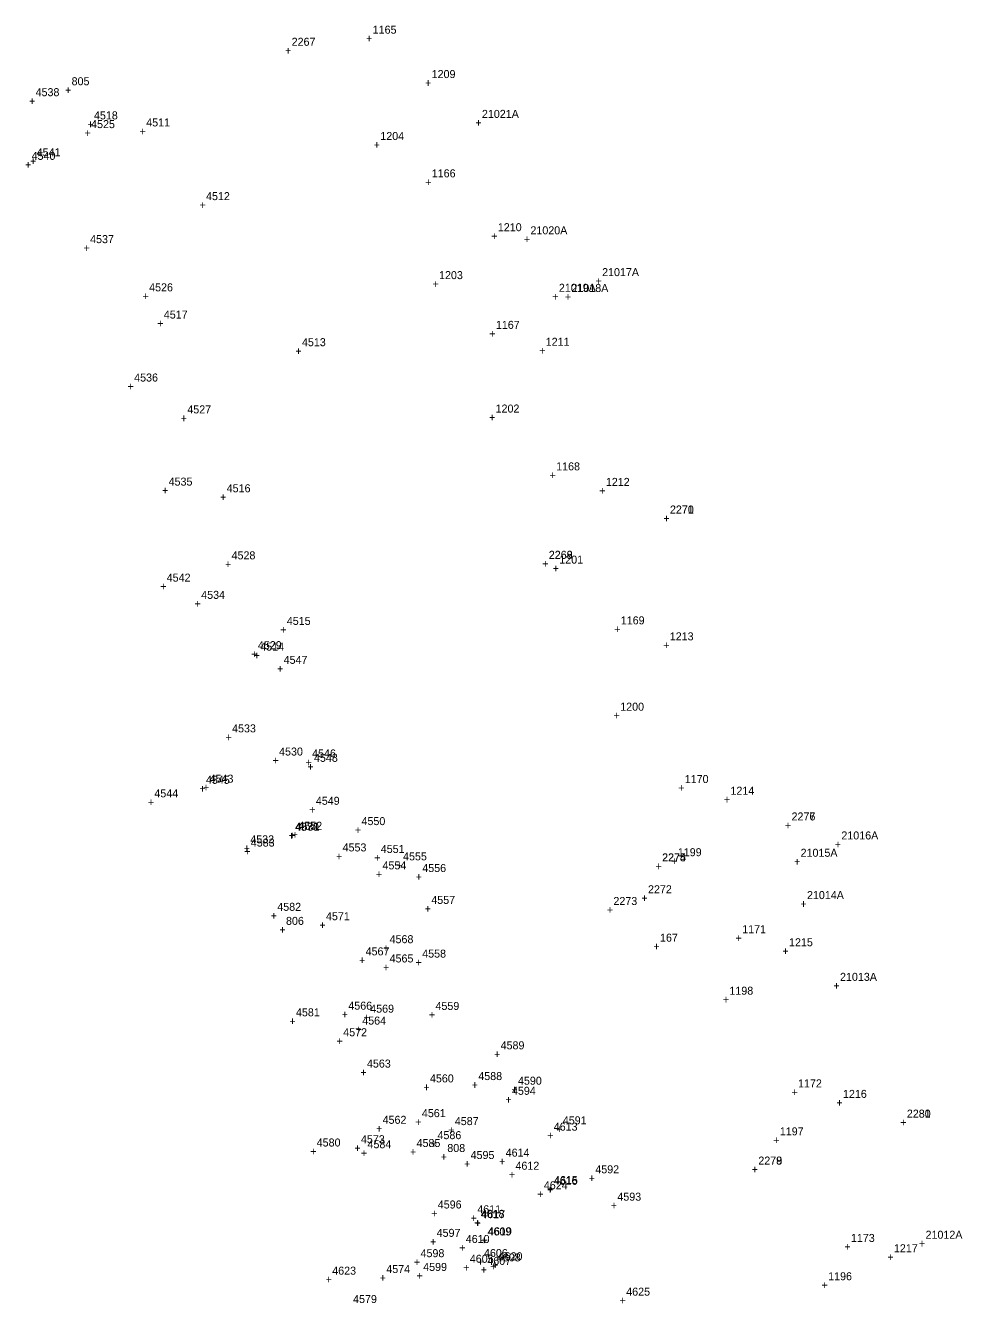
# Model space of a CAD drawing. Extents: x 1036751 to 1042192, y 772604 to 785439.
# Drawn here: x 1037171.7 to 1037464.4, y 782217.4 to 782616.6 of the extents above; entities that cross this region are included whole.
import ezdxf

# ---------------------------------------------------------------- set-up
doc = ezdxf.new("R2010")
doc.units = 0
for name, color, linetype in [('S_Buildings', 7, 'Continuous'), ('S_Buildings_SillElevation', 7, 'Continuous'), ('S_Control_Temp_Traverse', 7, 'Continuous'), ('S_Drainage_Culvert_Top', 7, 'Continuous'), ('S_Drainage_Invert', 7, 'Continuous'), ('S_Drainage_RipRap', 7, 'Continuous'), ('S_Ground_Elevation', 7, 'Continuous'), ('S_Property_BlazedLine', 7, 'Continuous'), ('S_Property_IronPipeFound', 7, 'Continuous'), ('S_Property_Well_Top', 7, 'Continuous'), ('S_Roadway_Centerline', 7, 'Continuous'), ('S_Roadway_Edge_Pavement', 7, 'Continuous'), ('S_Roadway_Edge_TW', 7, 'Continuous'), ('S_Utilities_Pole_Brace3', 7, 'Continuous'), ('S_Utilities_Pole_Power', 7, 'Continuous')]:
    doc.layers.add(name, color=color, linetype=linetype)

msp = doc.modelspace()

# ---------------------------------------------------------------- texts
at = {"layer": 'S_Buildings'}
for s, p in [('4616', (1037336.69, 782254.49)), ('+', (1037334.63, 782251.74)), ('4617', (1037314.1, 782244.07)), ('+', (1037312.04, 782241.32))]:
    msp.add_text(s, height=2.5, dxfattribs=at).set_placement(p)
at = {"layer": 'S_Buildings_SillElevation'}
for s, p in [('4624', (1037333.61, 782253.09)), ('+', (1037331.55, 782250.34))]:
    msp.add_text(s, height=2.5, dxfattribs=at).set_placement(p)
at = {"layer": 'S_Control_Temp_Traverse'}
for s, p in [('805', (1037186.13, 782597.95)), ('805', (1037186.13, 782597.95)), ('805', (1037186.13, 782597.95)), ('805', (1037186.13, 782597.95)), ('+', (1037184.07, 782595.2)), ('+', (1037184.07, 782595.2)), ('+', (1037184.07, 782595.2)), ('+', (1037184.07, 782595.2)), ('806', (1037253.09, 782335.68)), ('806', (1037253.09, 782335.68)), ('806', (1037253.09, 782335.68)), ('806', (1037253.09, 782335.68)), ('806', (1037253.09, 782335.68)), ('+', (1037251.03, 782332.93)), ('+', (1037251.03, 782332.93)), ('+', (1037251.03, 782332.93)), ('+', (1037251.03, 782332.93)), ('+', (1037251.03, 782332.93)), ('167', (1037369.9, 782330.44)), ('167', (1037369.9, 782330.44)), ('+', (1037367.83, 782327.69)), ('+', (1037367.83, 782327.69)), ('+', (1037301.41, 782261.99)), ('+', (1037301.41, 782261.99)), ('808', (1037303.47, 782264.74)), ('808', (1037303.47, 782264.74))]:
    msp.add_text(s, height=2.5, dxfattribs=at).set_placement(p)
at = {"layer": 'S_Drainage_Culvert_Top'}
for s, p in [('+', (1037370.96, 782461.43)), ('2270', (1037373.02, 782464.18)), ('2269', (1037335.16, 782450)), ('+', (1037333.09, 782447.25)), ('+', (1037408.92, 782365.55)), ('2276', (1037410.98, 782368.3)), ('2275', (1037370.55, 782355.54)), ('+', (1037368.49, 782352.79)), ('2280', (1037447, 782275.49)), ('+', (1037444.94, 782272.74)), ('+', (1037398.54, 782258.07)), ('2279', (1037400.6, 782260.82))]:
    msp.add_text(s, height=2.5, dxfattribs=at).set_placement(p)
at = {"layer": 'S_Drainage_Invert'}
for s, p in [('+', (1037370.93, 782461.41)), ('2271', (1037372.99, 782464.16)), ('2268', (1037335.17, 782450.03)), ('+', (1037333.11, 782447.28)), ('+', (1037408.92, 782365.56)), ('2277', (1037410.98, 782368.31)), ('2274', (1037370.57, 782355.49)), ('+', (1037368.51, 782352.74)), ('2281', (1037446.99, 782275.46)), ('+', (1037444.93, 782272.71)), ('+', (1037398.55, 782258.06)), ('2278', (1037400.61, 782260.81))]:
    msp.add_text(s, height=2.5, dxfattribs=at).set_placement(p)
at = {"layer": 'S_Drainage_RipRap'}
for s, p in [('+', (1037312.22, 782585)), ('21021A', (1037314.28, 782587.75)), ('21020A', (1037329.43, 782551.38)), ('+', (1037327.37, 782548.63)), ('21017A', (1037351.81, 782538.32)), ('21019A', (1037338.31, 782533.44)), ('21018A', (1037342.24, 782533.36)), ('+', (1037349.75, 782535.57)), ('+', (1037336.25, 782530.69)), ('+', (1037340.18, 782530.61)), ('21016A', (1037426.54, 782362.37)), ('21015A', (1037413.81, 782356.96)), ('+', (1037424.48, 782359.62)), ('+', (1037411.75, 782354.21)), ('21014A', (1037415.8, 782343.75)), ('+', (1037413.74, 782341)), ('21013A', (1037426.12, 782318.2)), ('+', (1037424.06, 782315.45)), ('21012A', (1037452.83, 782237.65)), ('+', (1037450.77, 782234.9))]:
    msp.add_text(s, height=2.5, dxfattribs=at).set_placement(p)
at = {"layer": 'S_Ground_Elevation'}
for s, p in [('4518', (1037193.11, 782587.28)), ('4511', (1037209.43, 782585.08)), ('+', (1037191.05, 782584.53)), ('+', (1037207.36, 782582.33)), ('4512', (1037228.12, 782562.06)), ('+', (1037226.06, 782559.31)), ('4517', (1037214.93, 782525.07)), ('+', (1037212.87, 782522.32)), ('+', (1037256.01, 782513.69)), ('4513', (1037258.07, 782516.44)), ('4516', (1037234.57, 782470.81)), ('+', (1037232.5, 782468.06)), ('4515', (1037253.34, 782429.38)), ('+', (1037251.28, 782426.63)), ('4514', (1037245.05, 782421.36)), ('+', (1037242.99, 782418.61)), ('4547', (1037252.35, 782417.22)), ('+', (1037250.29, 782414.47)), ('4548', (1037261.83, 782386.61)), ('+', (1037259.77, 782383.86)), ('4549', (1037262.41, 782373.2)), ('+', (1037260.35, 782370.45)), ('4552', (1037256.95, 782365.4)), ('4550', (1037276.67, 782366.85)), ('+', (1037254.89, 782362.65)), ('+', (1037274.61, 782364.1)), ('4553', (1037270.76, 782358.63)), ('4551', (1037282.69, 782358.15)), ('+', (1037268.7, 782355.88)), ('+', (1037280.62, 782355.4)), ('4554', (1037283.22, 782353.02)), ('4555', (1037289.65, 782355.84)), ('+', (1037281.16, 782350.27)), ('+', (1037287.59, 782353.09)), ('+', (1037293.59, 782349.44)), ('4556', (1037295.65, 782352.19)), ('4557', (1037298.47, 782342.23)), ('+', (1037296.4, 782339.48)), ('4568', (1037285.44, 782329.96)), ('4567', (1037277.95, 782326.16)), ('+', (1037283.38, 782327.21)), ('4558', (1037295.63, 782325.46)), ('+', (1037275.89, 782323.41)), ('4565', (1037285.44, 782323.95)), ('+', (1037293.57, 782322.71)), ('+', (1037283.38, 782321.2)), ('4566', (1037272.55, 782309.2)), ('4559', (1037299.77, 782309.11)), ('+', (1037270.48, 782306.45)), ('+', (1037297.71, 782306.36)), ('+', (1037274.84, 782301.78)), ('4564', (1037276.9, 782304.53)), ('+', (1037318.06, 782294.06)), ('4589', (1037320.12, 782296.81)), ('4563', (1037278.37, 782291.11)), ('+', (1037276.31, 782288.36)), ('4560', (1037298.04, 782286.48)), ('4588', (1037313.15, 782287.21)), ('4590', (1037325.54, 782285.76)), ('+', (1037295.98, 782283.73)), ('+', (1037311.09, 782284.46)), ('+', (1037323.48, 782283.01)), ('4594', (1037323.66, 782282.61)), ('+', (1037321.6, 782279.86)), ('4562', (1037283.26, 782273.55)), ('4561', (1037295.53, 782275.63)), ('4587', (1037305.81, 782273.14)), ('4591', (1037339.54, 782273.38)), ('+', (1037281.2, 782270.8)), ('+', (1037293.47, 782272.88)), ('+', (1037303.75, 782270.39)), ('4613', (1037336.71, 782271.4)), ('+', (1037337.48, 782270.63)), ('4584', (1037278.54, 782265.92)), ('4585', (1037293.87, 782266.3)), ('+', (1037298.34, 782266.02)), ('4586', (1037300.4, 782268.76)), ('+', (1037334.65, 782268.66)), ('+', (1037276.48, 782263.17)), ('+', (1037291.81, 782263.55)), ('4595', (1037310.74, 782262.55)), ('+', (1037308.68, 782259.8)), ('4612', (1037324.75, 782259.2)), ('4592', (1037349.69, 782258.08)), ('+', (1037322.69, 782256.45)), ('4615', (1037336.81, 782254.76)), ('+', (1037347.63, 782255.33)), ('+', (1037334.75, 782252.01)), ('4593', (1037356.58, 782249.54)), ('4596', (1037300.49, 782247.1)), ('4611', (1037312.83, 782245.6)), ('+', (1037354.52, 782246.79)), ('+', (1037298.43, 782244.35)), ('+', (1037310.76, 782242.85)), ('4618', (1037313.9, 782244.17)), ('4597', (1037300.14, 782238.24)), ('+', (1037311.84, 782241.42)), ('4609', (1037316.03, 782238.67)), ('4619', (1037316.2, 782238.73)), ('+', (1037298.08, 782235.49)), ('+', (1037307.17, 782233.58)), ('4610', (1037309.23, 782236.33)), ('+', (1037313.97, 782235.92)), ('+', (1037314.14, 782235.98)), ('4598', (1037295.11, 782231.89)), ('4605', (1037310.5, 782230.14)), ('4606', (1037314.92, 782231.94)), ('4607', (1037315.96, 782229.49)), ('4608', (1037318.95, 782230.57)), ('4620', (1037319.5, 782230.93)), ('+', (1037293.05, 782229.14)), ('4599', (1037295.93, 782227.59)), ('+', (1037308.44, 782227.39)), ('+', (1037312.86, 782229.19)), ('+', (1037313.9, 782226.74)), ('+', (1037316.89, 782227.82)), ('+', (1037317.44, 782228.18)), ('+', (1037293.87, 782224.84)), ('4625', (1037359.35, 782219.87)), ('+', (1037357.29, 782217.12))]:
    msp.add_text(s, height=2.5, dxfattribs=at).set_placement(p)
at = {"layer": 'S_Property_BlazedLine'}
for s, p in [('4546', (1037261.24, 782387.99)), ('+', (1037259.18, 782385.24)), ('4545', (1037228.08, 782379.75)), ('4544', (1037211.98, 782375.52)), ('+', (1037226.02, 782377)), ('+', (1037209.92, 782372.77))]:
    msp.add_text(s, height=2.5, dxfattribs=at).set_placement(p)
at = {"layer": 'S_Property_IronPipeFound'}
for s, p in [('4540', (1037173.64, 782574.64)), ('+', (1037171.58, 782571.89)), ('+', (1037227.16, 782377.35)), ('4543', (1037229.23, 782380.1))]:
    msp.add_text(s, height=2.5, dxfattribs=at).set_placement(p)
at = {"layer": 'S_Property_Well_Top'}
for s, p in [('4614', (1037321.69, 782263.29)), ('+', (1037319.63, 782260.54)), ('4623', (1037267.53, 782226.43)), ('+', (1037265.47, 782223.68))]:
    msp.add_text(s, height=2.5, dxfattribs=at).set_placement(p)
at = {"layer": 'S_Roadway_Centerline'}
for s, p in [('1165', (1037280.16, 782614.05)), ('+', (1037278.09, 782611.3)), ('1166', (1037298.61, 782569.18)), ('+', (1037296.55, 782566.43)), ('1167', (1037318.64, 782521.85)), ('+', (1037316.58, 782519.1)), ('1168', (1037337.47, 782477.65)), ('+', (1037335.41, 782474.9)), ('1169', (1037357.65, 782429.55)), ('+', (1037355.59, 782426.8)), ('1170', (1037377.63, 782379.99)), ('+', (1037375.57, 782377.24)), ('1171', (1037395.57, 782333.08)), ('+', (1037393.51, 782330.33)), ('+', (1037410.95, 782282.18)), ('1172', (1037413.01, 782284.93)), ('+', (1037427.46, 782233.9)), ('1173', (1037429.52, 782236.65))]:
    msp.add_text(s, height=2.5, dxfattribs=at).set_placement(p)
at = {"layer": 'S_Roadway_Edge_Pavement'}
for s, p in [('+', (1037296.52, 782597.44)), ('1209', (1037298.58, 782600.19)), ('1204', (1037282.55, 782580.84)), ('+', (1037280.49, 782578.09)), ('+', (1037317.19, 782549.6)), ('1210', (1037319.25, 782552.35)), ('1203', (1037300.89, 782537.39)), ('+', (1037298.83, 782534.64)), ('1211', (1037334.2, 782516.56)), ('+', (1037332.14, 782513.81)), ('1202', (1037318.55, 782495.71)), ('+', (1037316.49, 782492.96)), ('1212', (1037352.99, 782472.8)), ('+', (1037350.93, 782470.05)), ('+', (1037336.38, 782445.77)), ('1201', (1037338.44, 782448.52)), ('+', (1037370.88, 782421.82)), ('1213', (1037372.94, 782424.56)), ('1200', (1037357.47, 782402.58)), ('+', (1037355.41, 782399.83)), ('+', (1037389.84, 782373.59)), ('1214', (1037391.9, 782376.34)), ('1199', (1037375.46, 782357.13)), ('+', (1037373.4, 782354.38)), ('1215', (1037410.19, 782329.01)), ('+', (1037408.13, 782326.26)), ('1198', (1037391.57, 782313.87)), ('+', (1037389.51, 782311.12)), ('1216', (1037427.04, 782281.64)), ('+', (1037424.98, 782278.89)), ('1197', (1037407.32, 782269.94)), ('+', (1037405.26, 782267.19)), ('1217', (1037442.95, 782233.43)), ('+', (1037440.89, 782230.68)), ('+', (1037420.36, 782221.93)), ('1196', (1037422.42, 782224.68))]:
    msp.add_text(s, height=2.5, dxfattribs=at).set_placement(p)
at = {"layer": 'S_Roadway_Edge_TW'}
for s, p in [('4538', (1037174.88, 782594.53)), ('+', (1037172.82, 782591.78)), ('4525', (1037192.22, 782584.56)), ('+', (1037190.16, 782581.81)), ('4537', (1037191.91, 782548.63)), ('+', (1037189.84, 782545.88)), ('4526', (1037210.34, 782533.58)), ('+', (1037208.28, 782530.83)), ('4536', (1037205.67, 782505.4)), ('+', (1037203.61, 782502.65)), ('4527', (1037222.27, 782495.45)), ('+', (1037220.21, 782492.7)), ('4535', (1037216.43, 782472.89)), ('+', (1037214.37, 782470.14)), ('4528', (1037236.09, 782449.86)), ('+', (1037234.03, 782447.11)), ('4534', (1037226.6, 782437.52)), ('+', (1037224.54, 782434.77)), ('4529', (1037244.31, 782421.8)), ('+', (1037242.25, 782419.05)), ('4533', (1037236.25, 782395.81)), ('+', (1037234.19, 782393.06)), ('+', (1037248.87, 782385.83)), ('4530', (1037250.93, 782388.58)), ('4570', (1037255.89, 782365.08)), ('4531', (1037256.09, 782365.13)), ('4532', (1037241.93, 782361.15)), ('+', (1037253.83, 782362.33)), ('+', (1037254.03, 782362.38)), ('+', (1037239.87, 782358.4)), ('+', (1037240.03, 782357.39)), ('4583', (1037242.09, 782360.14)), ('4582', (1037250.36, 782340.07)), ('4571', (1037265.57, 782337.14)), ('+', (1037248.3, 782337.32)), ('+', (1037263.51, 782334.39)), ('4581', (1037256.2, 782307.12)), ('+', (1037254.14, 782304.37)), ('+', (1037268.9, 782298.15)), ('4572', (1037270.96, 782300.9)), ('4580', (1037262.68, 782266.46)), ('4573', (1037276.49, 782267.48)), ('+', (1037260.62, 782263.71)), ('+', (1037274.43, 782264.73)), ('4574', (1037284.41, 782226.94)), ('+', (1037282.35, 782224.19)), ('4579', (1037274.04, 782217.57))]:
    msp.add_text(s, height=2.5, dxfattribs=at).set_placement(p)
at = {"layer": 'S_Utilities_Pole_Brace3'}
for s, p in [('2273', (1037355.35, 782341.89)), ('+', (1037353.29, 782339.14))]:
    msp.add_text(s, height=2.5, dxfattribs=at).set_placement(p)
at = {"layer": 'S_Utilities_Pole_Power'}
for s, p in [('2267', (1037254.85, 782610.28)), ('+', (1037252.79, 782607.53)), ('+', (1037173.15, 782573)), ('4541', (1037175.22, 782575.75)), ('4542', (1037215.83, 782442.9)), ('+', (1037213.77, 782440.15)), ('2272', (1037366.15, 782345.56)), ('+', (1037364.09, 782342.81)), ('+', (1037277.33, 782305.51)), ('4569', (1037279.39, 782308.26))]:
    msp.add_text(s, height=2.5, dxfattribs=at).set_placement(p)

doc.saveas('drawing.dxf')
